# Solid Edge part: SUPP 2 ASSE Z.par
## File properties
Subject: SUPP 2 ASSE Z
Author: f_grande
Template: Normal.par
Last saved by: f_grande
Revision: 18
Application: Solid Edge
Material: MDF
Stile della faccia: Marroncino
Coef. of Thermal Exp: 0.0
Thermal Conductivity: 0.0
Specific Heat: 0.0
Modulus of Elasticity: 0.0
Poisson's Ratio: 0.0
Yield Stress: 0.0
Ultimate Stress: 0.0
Elongation: 0.0
Tipo di contenuto documento: 0
Densità: 750,000 kg/m^3
Precisione: 0,990
Document Number: KR0140
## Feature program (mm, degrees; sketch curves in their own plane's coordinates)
sketch for "unnamed Protrusion 1" plane through (0, 0, 0) normal (0, -1, 0) x-axis (1, 0, 0)
  line (-25.9347, 40.8076) -> (99.0653, 40.8076)
  line (99.0653, 40.8076) -> (99.0653, -199.1924)
  line (99.0653, -199.1924) -> (-25.9347, -199.1924)
  line (-25.9347, -199.1924) -> (-25.9347, 40.8076)
  dimension (linear) = 25.9347
  dimension (linear) = 25.9347
extrude "unnamed Protrusion 1" add finite 19 along +normal
sketch for "Foro_4" plane through (37.5653, -19, -79.1924) normal (0, -1, 0) x-axis (1, 0, 0)
  hole centre (51.5, 110.5) bore radius 2
hole "Foro_4" diameter 4 through
sketch for "unnamed Hole 1" plane through (37.5653, -19, -79.1924) normal (0, -1, 0) x-axis (1, 0, 0)
  hole centre (-1, 110.5) bore radius 2
hole "unnamed Hole 1" through
sketch for "unnamed Hole 2" plane through (37.5653, -19, -79.1924) normal (0, -1, 0) x-axis (1, 0, 0)
hole "unnamed Hole 2" through
sketch for "Foro_7" plane through (36.5653, -19, -79.1924) normal (0, -1, 0) x-axis (1, 0, 0)
  hole centre (56.5, -94) bore radius 2
hole "Foro_7" diameter 4 through
sketch for "unnamed Hole 3" plane through (36.5653, -19, -79.1924) normal (0, -1, 0) x-axis (1, 0, 0)
  hole centre (26.5, -94) bore radius 2
hole "unnamed Hole 3" through
sketch for "unnamed Hole 4" plane through (36.5653, -19, -79.1924) normal (0, -1, 0) x-axis (1, 0, 0)
  hole centre (26.5, -44) bore radius 2
hole "unnamed Hole 4" through
sketch for "unnamed Hole 5" plane through (36.5653, -19, -79.1924) normal (0, -1, 0) x-axis (1, 0, 0)
  hole centre (-26.5, -94) bore radius 2
hole "unnamed Hole 5" through
sketch for "unnamed Hole 6" plane through (36.5653, -19, -79.1924) normal (0, -1, 0) x-axis (1, 0, 0)
  hole centre (-26.5, -44) bore radius 2
hole "unnamed Hole 6" through
sketch for "unnamed Hole 7" plane through (36.5653, -19, -79.1924) normal (0, -1, 0) x-axis (1, 0, 0)
  hole centre (-56.5, -44) bore radius 2
hole "unnamed Hole 7" through
sketch for "unnamed Hole 8" plane through (36.5653, -19, -79.1924) normal (0, -1, 0) x-axis (1, 0, 0)
  hole centre (-56.5, -94) bore radius 2
hole "unnamed Hole 8" through
sketch for "unnamed Hole 9" plane through (36.5653, -19, -79.1924) normal (0, -1, 0) x-axis (1, 0, 0)
  hole centre (56.5, -44) bore radius 2
hole "unnamed Hole 9" through
chamfer "Smusso_1" setback 2
chamfer "Smusso_2" setback 2
sketch for "Foro_15" plane through (36.5653, -19, -79.1924) normal (0, -1, 0) x-axis (-1, 0, 0)
hole "Foro_15" diameter 6.5 through  CounterSinkAngle = 82 deg
sketch for "unnamed Hole 10" plane through (36.5653, -19, -79.1924) normal (0, -1, 0) x-axis (-1, 0, 0)
hole "unnamed Hole 10" through
pattern "unnamed Pattern 1" of "Foro_15", "unnamed Hole 10"
pattern "unnamed Pattern 2" of "Foro_4", "unnamed Hole 1", "unnamed Hole 2"
pattern "unnamed Pattern 3" of "Foro_7", "unnamed Hole 3", "unnamed Hole 4", "unnamed Hole 5", "unnamed Hole 6", "unnamed Hole 7", "unnamed Hole 8", "unnamed Hole 9"
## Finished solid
Body 1: solid body, 32 faces, 51 edges, 8 vertices.
  Faces by surface: cone 13, cylinder 13, plane 6
  Edges by curve: circle 39, line 12
Bounding box of the edges (mm): 125.000 x 19.000 x 240.000, from (-25.9347, -19, -199.1924) to (99.0653, 0, 40.8076).
Cylindrical faces by radius (mm): R2 x11, R3.25 x2
Conical faces (half-angle, radius in mm at the cone's reference point): 41 deg R6.35 x2, 45 deg R2 x11
Planar faces by outward normal: +x 1, +y 1, +z 1, -x 1, -y 1, -z 1
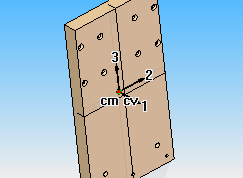
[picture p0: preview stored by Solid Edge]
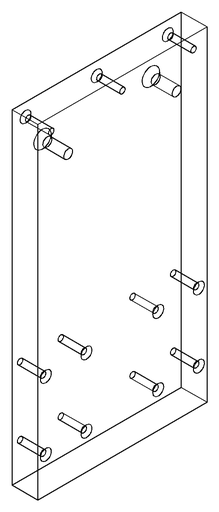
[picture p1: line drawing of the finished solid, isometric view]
